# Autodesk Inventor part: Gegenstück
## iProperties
Created: 2007-04
Part Number: Gegenstück
Document SubType Name: Sheet Metal
Designer: Benno
Manufacturer: Standard
Standards Organization: Custom
Author: Benno
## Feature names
1. Bohrung1 [Hole]
2. Bohrung2 [Hole]
3. Grobblech1
4. Grobblech3
5. Biegung2
6. ExtrusionAbwicklung1
